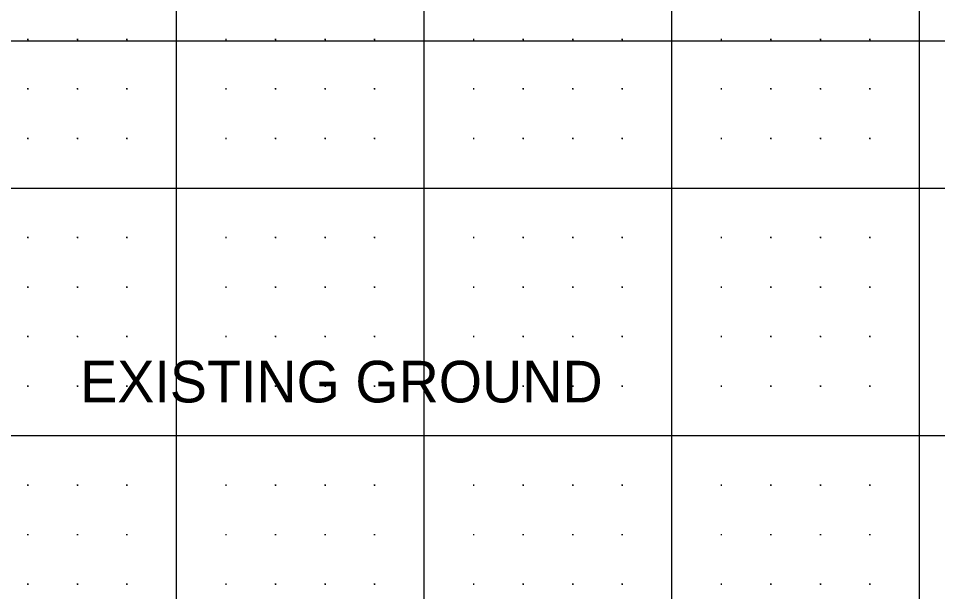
# Model space of a CAD drawing. Extents: x 471 to 2121, y 140 to 650.
# Drawn here: x 1754.2 to 1939.7, y 418.5 to 534.3 of the extents above; entities that cross this region are included whole.
import ezdxf

# ---------------------------------------------------------------- set-up
doc = ezdxf.new("R2010")
doc.units = 0
for name, color, linetype in [('Default', 7, 'Continuous'), ('DSN_DRFT_Border Grid', 7, 'Continuous'), ('Transition Dimensions', 7, 'Continuous')]:
    doc.layers.add(name, color=color, linetype=linetype)

msp = doc.modelspace()

# ---------------------------------------------------------------- linework, layer by layer
at = {"layer": 'DSN_DRFT_Border Grid'}
for p, q in [((1786.06, 150), (1786.06, 650)), ((1786.06, 150), (1786.06, 650)), ((1836.06, 150), (1836.06, 650)), ((1836.06, 150), (1836.06, 650)), ((1886.06, 150), (1886.06, 650)), ((1886.06, 150), (1886.06, 650)), ((1936.06, 150), (1936.06, 650)), ((1936.06, 150), (1936.06, 650)), ((1756.18, 530), (1755.94, 530)), ((1756.18, 530), (1755.94, 530)), ((1756.06, 530.12), (1756.06, 529.88)), ((1756.06, 530.12), (1756.06, 529.88)), ((1766.18, 530), (1765.94, 530)), ((1766.18, 530), (1765.94, 530)), ((1766.06, 530.12), (1766.06, 529.88)), ((1766.06, 530.12), (1766.06, 529.88)), ((1776.18, 530), (1775.94, 530)), ((1776.18, 530), (1775.94, 530)), ((1776.06, 530.12), (1776.06, 529.88)), ((1776.06, 530.12), (1776.06, 529.88)), ((1796.18, 530), (1795.94, 530)), ((1796.18, 530), (1795.94, 530)), ((1796.06, 530.12), (1796.06, 529.88)), ((1796.06, 530.12), (1796.06, 529.88)), ((1806.18, 530), (1805.94, 530)), ((1806.18, 530), (1805.94, 530)), ((1806.06, 530.12), (1806.06, 529.88)), ((1806.06, 530.12), (1806.06, 529.88)), ((1816.18, 530), (1815.94, 530)), ((1816.18, 530), (1815.94, 530)), ((1816.06, 530.12), (1816.06, 529.88)), ((1816.06, 530.12), (1816.06, 529.88)), ((1826.18, 530), (1825.94, 530)), ((1826.18, 530), (1825.94, 530)), ((1826.06, 530.12), (1826.06, 529.88)), ((1826.06, 530.12), (1826.06, 529.88)), ((1846.18, 530), (1845.94, 530)), ((1846.18, 530), (1845.94, 530)), ((1846.06, 530.12), (1846.06, 529.88)), ((1846.06, 530.12), (1846.06, 529.88)), ((1856.18, 530), (1855.94, 530)), ((1856.18, 530), (1855.94, 530)), ((1856.06, 530.12), (1856.06, 529.88)), ((1856.06, 530.12), (1856.06, 529.88)), ((1866.18, 530), (1865.94, 530)), ((1866.18, 530), (1865.94, 530)), ((1866.06, 530.12), (1866.06, 529.88)), ((1866.06, 530.12), (1866.06, 529.88)), ((1876.18, 530), (1875.94, 530)), ((1876.18, 530), (1875.94, 530)), ((1876.06, 530.12), (1876.06, 529.88)), ((1876.06, 530.12), (1876.06, 529.88)), ((1896.18, 530), (1895.94, 530)), ((1896.18, 530), (1895.94, 530)), ((1896.06, 530.12), (1896.06, 529.88)), ((1896.06, 530.12), (1896.06, 529.88)), ((1906.18, 530), (1905.94, 530)), ((1906.18, 530), (1905.94, 530)), ((1906.06, 530.12), (1906.06, 529.88)), ((1906.06, 530.12), (1906.06, 529.88)), ((1916.18, 530), (1915.94, 530)), ((1916.18, 530), (1915.94, 530)), ((1916.06, 530.12), (1916.06, 529.88)), ((1916.06, 530.12), (1916.06, 529.88)), ((1926.18, 530), (1925.94, 530)), ((1926.18, 530), (1925.94, 530)), ((1926.06, 530.12), (1926.06, 529.88)), ((1926.06, 530.12), (1926.06, 529.88)), ((1756.18, 520), (1755.94, 520)), ((1756.18, 520), (1755.94, 520)), ((1756.06, 520.12), (1756.06, 519.88)), ((1756.06, 520.12), (1756.06, 519.88)), ((1766.18, 520), (1765.94, 520)), ((1766.18, 520), (1765.94, 520)), ((1766.06, 520.12), (1766.06, 519.88)), ((1766.06, 520.12), (1766.06, 519.88)), ((1776.18, 520), (1775.94, 520)), ((1776.18, 520), (1775.94, 520)), ((1776.06, 520.12), (1776.06, 519.88)), ((1776.06, 520.12), (1776.06, 519.88)), ((1796.18, 520), (1795.94, 520)), ((1796.18, 520), (1795.94, 520)), ((1796.06, 520.12), (1796.06, 519.88)), ((1796.06, 520.12), (1796.06, 519.88)), ((1806.18, 520), (1805.94, 520)), ((1806.18, 520), (1805.94, 520)), ((1806.06, 520.12), (1806.06, 519.88)), ((1806.06, 520.12), (1806.06, 519.88)), ((1816.18, 520), (1815.94, 520)), ((1816.18, 520), (1815.94, 520)), ((1816.06, 520.12), (1816.06, 519.88)), ((1816.06, 520.12), (1816.06, 519.88)), ((1826.18, 520), (1825.94, 520)), ((1826.18, 520), (1825.94, 520)), ((1826.06, 520.12), (1826.06, 519.88)), ((1826.06, 520.12), (1826.06, 519.88)), ((1846.18, 520), (1845.94, 520)), ((1846.18, 520), (1845.94, 520)), ((1846.06, 520.12), (1846.06, 519.88)), ((1846.06, 520.12), (1846.06, 519.88)), ((1856.18, 520), (1855.94, 520)), ((1856.18, 520), (1855.94, 520)), ((1856.06, 520.12), (1856.06, 519.88)), ((1856.06, 520.12), (1856.06, 519.88)), ((1866.18, 520), (1865.94, 520)), ((1866.18, 520), (1865.94, 520)), ((1866.06, 520.12), (1866.06, 519.88)), ((1866.06, 520.12), (1866.06, 519.88)), ((1876.18, 520), (1875.94, 520)), ((1876.18, 520), (1875.94, 520)), ((1876.06, 520.12), (1876.06, 519.88)), ((1876.06, 520.12), (1876.06, 519.88)), ((1896.18, 520), (1895.94, 520)), ((1896.18, 520), (1895.94, 520)), ((1896.06, 520.12), (1896.06, 519.88)), ((1896.06, 520.12), (1896.06, 519.88)), ((1906.18, 520), (1905.94, 520)), ((1906.18, 520), (1905.94, 520)), ((1906.06, 520.12), (1906.06, 519.88)), ((1906.06, 520.12), (1906.06, 519.88)), ((1916.18, 520), (1915.94, 520)), ((1916.18, 520), (1915.94, 520)), ((1916.06, 520.12), (1916.06, 519.88)), ((1916.06, 520.12), (1916.06, 519.88)), ((1926.18, 520), (1925.94, 520)), ((1926.18, 520), (1925.94, 520)), ((1926.06, 520.12), (1926.06, 519.88)), ((1926.06, 520.12), (1926.06, 519.88)), ((1756.18, 510), (1755.94, 510)), ((1756.18, 510), (1755.94, 510)), ((1756.06, 510.12), (1756.06, 509.88)), ((1756.06, 510.12), (1756.06, 509.88)), ((1766.18, 510), (1765.94, 510)), ((1766.18, 510), (1765.94, 510)), ((1766.06, 510.12), (1766.06, 509.88)), ((1766.06, 510.12), (1766.06, 509.88)), ((1776.18, 510), (1775.94, 510)), ((1776.18, 510), (1775.94, 510)), ((1776.06, 510.12), (1776.06, 509.88)), ((1776.06, 510.12), (1776.06, 509.88)), ((1796.18, 510), (1795.94, 510)), ((1796.18, 510), (1795.94, 510)), ((1796.06, 510.12), (1796.06, 509.88)), ((1796.06, 510.12), (1796.06, 509.88)), ((1806.18, 510), (1805.94, 510)), ((1806.18, 510), (1805.94, 510)), ((1806.06, 510.12), (1806.06, 509.88)), ((1806.06, 510.12), (1806.06, 509.88)), ((1816.18, 510), (1815.94, 510)), ((1816.18, 510), (1815.94, 510)), ((1816.06, 510.12), (1816.06, 509.88)), ((1816.06, 510.12), (1816.06, 509.88)), ((1826.18, 510), (1825.94, 510)), ((1826.18, 510), (1825.94, 510)), ((1826.06, 510.12), (1826.06, 509.88)), ((1826.06, 510.12), (1826.06, 509.88)), ((1846.18, 510), (1845.94, 510)), ((1846.18, 510), (1845.94, 510)), ((1846.06, 510.12), (1846.06, 509.88)), ((1846.06, 510.12), (1846.06, 509.88)), ((1856.18, 510), (1855.94, 510)), ((1856.18, 510), (1855.94, 510)), ((1856.06, 510.12), (1856.06, 509.88)), ((1856.06, 510.12), (1856.06, 509.88)), ((1866.18, 510), (1865.94, 510)), ((1866.18, 510), (1865.94, 510)), ((1866.06, 510.12), (1866.06, 509.88)), ((1866.06, 510.12), (1866.06, 509.88)), ((1876.18, 510), (1875.94, 510)), ((1876.18, 510), (1875.94, 510)), ((1876.06, 510.12), (1876.06, 509.88)), ((1876.06, 510.12), (1876.06, 509.88)), ((1896.18, 510), (1895.94, 510)), ((1896.18, 510), (1895.94, 510)), ((1896.06, 510.12), (1896.06, 509.88)), ((1896.06, 510.12), (1896.06, 509.88)), ((1906.18, 510), (1905.94, 510)), ((1906.18, 510), (1905.94, 510)), ((1906.06, 510.12), (1906.06, 509.88)), ((1906.06, 510.12), (1906.06, 509.88)), ((1916.18, 510), (1915.94, 510)), ((1916.18, 510), (1915.94, 510)), ((1916.06, 510.12), (1916.06, 509.88)), ((1916.06, 510.12), (1916.06, 509.88)), ((1926.18, 510), (1925.94, 510)), ((1926.18, 510), (1925.94, 510)), ((1926.06, 510.12), (1926.06, 509.88)), ((1926.06, 510.12), (1926.06, 509.88)), ((521.06, 500), (2071.06, 500)), ((521.06, 500), (2071.06, 500)), ((1756.18, 490), (1755.94, 490)), ((1756.18, 490), (1755.94, 490)), ((1756.06, 490.12), (1756.06, 489.88)), ((1756.06, 490.12), (1756.06, 489.88)), ((1766.18, 490), (1765.94, 490)), ((1766.18, 490), (1765.94, 490)), ((1766.06, 490.12), (1766.06, 489.88)), ((1766.06, 490.12), (1766.06, 489.88)), ((1776.18, 490), (1775.94, 490)), ((1776.18, 490), (1775.94, 490)), ((1776.06, 490.12), (1776.06, 489.88)), ((1776.06, 490.12), (1776.06, 489.88)), ((1796.18, 490), (1795.94, 490)), ((1796.18, 490), (1795.94, 490)), ((1796.06, 490.12), (1796.06, 489.88)), ((1796.06, 490.12), (1796.06, 489.88)), ((1806.18, 490), (1805.94, 490)), ((1806.18, 490), (1805.94, 490)), ((1806.06, 490.12), (1806.06, 489.88)), ((1806.06, 490.12), (1806.06, 489.88)), ((1816.18, 490), (1815.94, 490)), ((1816.18, 490), (1815.94, 490)), ((1816.06, 490.12), (1816.06, 489.88)), ((1816.06, 490.12), (1816.06, 489.88)), ((1826.18, 490), (1825.94, 490)), ((1826.18, 490), (1825.94, 490)), ((1826.06, 490.12), (1826.06, 489.88)), ((1826.06, 490.12), (1826.06, 489.88)), ((1846.18, 490), (1845.94, 490)), ((1846.18, 490), (1845.94, 490)), ((1846.06, 490.12), (1846.06, 489.88)), ((1846.06, 490.12), (1846.06, 489.88)), ((1856.18, 490), (1855.94, 490)), ((1856.18, 490), (1855.94, 490)), ((1856.06, 490.12), (1856.06, 489.88)), ((1856.06, 490.12), (1856.06, 489.88)), ((1866.18, 490), (1865.94, 490)), ((1866.18, 490), (1865.94, 490)), ((1866.06, 490.12), (1866.06, 489.88)), ((1866.06, 490.12), (1866.06, 489.88)), ((1876.18, 490), (1875.94, 490)), ((1876.18, 490), (1875.94, 490)), ((1876.06, 490.12), (1876.06, 489.88)), ((1876.06, 490.12), (1876.06, 489.88)), ((1896.18, 490), (1895.94, 490)), ((1896.18, 490), (1895.94, 490)), ((1896.06, 490.12), (1896.06, 489.88)), ((1896.06, 490.12), (1896.06, 489.88)), ((1906.18, 490), (1905.94, 490)), ((1906.18, 490), (1905.94, 490)), ((1906.06, 490.12), (1906.06, 489.88)), ((1906.06, 490.12), (1906.06, 489.88)), ((1916.18, 490), (1915.94, 490)), ((1916.18, 490), (1915.94, 490)), ((1916.06, 490.12), (1916.06, 489.88)), ((1916.06, 490.12), (1916.06, 489.88)), ((1926.18, 490), (1925.94, 490)), ((1926.18, 490), (1925.94, 490)), ((1926.06, 490.12), (1926.06, 489.88)), ((1926.06, 490.12), (1926.06, 489.88)), ((1756.18, 480), (1755.94, 480)), ((1756.18, 480), (1755.94, 480)), ((1756.06, 480.12), (1756.06, 479.88)), ((1756.06, 480.12), (1756.06, 479.88)), ((1766.18, 480), (1765.94, 480)), ((1766.18, 480), (1765.94, 480)), ((1766.06, 480.12), (1766.06, 479.88)), ((1766.06, 480.12), (1766.06, 479.88)), ((1776.18, 480), (1775.94, 480)), ((1776.18, 480), (1775.94, 480)), ((1776.06, 480.12), (1776.06, 479.88)), ((1776.06, 480.12), (1776.06, 479.88)), ((1796.18, 480), (1795.94, 480)), ((1796.18, 480), (1795.94, 480)), ((1796.06, 480.12), (1796.06, 479.88)), ((1796.06, 480.12), (1796.06, 479.88)), ((1806.18, 480), (1805.94, 480)), ((1806.18, 480), (1805.94, 480)), ((1806.06, 480.12), (1806.06, 479.88)), ((1806.06, 480.12), (1806.06, 479.88)), ((1816.18, 480), (1815.94, 480)), ((1816.18, 480), (1815.94, 480)), ((1816.06, 480.12), (1816.06, 479.88)), ((1816.06, 480.12), (1816.06, 479.88)), ((1826.18, 480), (1825.94, 480)), ((1826.18, 480), (1825.94, 480)), ((1826.06, 480.12), (1826.06, 479.88)), ((1826.06, 480.12), (1826.06, 479.88)), ((1846.18, 480), (1845.94, 480)), ((1846.18, 480), (1845.94, 480)), ((1846.06, 480.12), (1846.06, 479.88)), ((1846.06, 480.12), (1846.06, 479.88)), ((1856.18, 480), (1855.94, 480)), ((1856.18, 480), (1855.94, 480)), ((1856.06, 480.12), (1856.06, 479.88)), ((1856.06, 480.12), (1856.06, 479.88)), ((1866.18, 480), (1865.94, 480)), ((1866.18, 480), (1865.94, 480)), ((1866.06, 480.12), (1866.06, 479.88)), ((1866.06, 480.12), (1866.06, 479.88)), ((1876.18, 480), (1875.94, 480)), ((1876.18, 480), (1875.94, 480)), ((1876.06, 480.12), (1876.06, 479.88)), ((1876.06, 480.12), (1876.06, 479.88)), ((1896.18, 480), (1895.94, 480)), ((1896.18, 480), (1895.94, 480)), ((1896.06, 480.12), (1896.06, 479.88)), ((1896.06, 480.12), (1896.06, 479.88)), ((1906.18, 480), (1905.94, 480)), ((1906.18, 480), (1905.94, 480)), ((1906.06, 480.12), (1906.06, 479.88)), ((1906.06, 480.12), (1906.06, 479.88)), ((1916.18, 480), (1915.94, 480)), ((1916.18, 480), (1915.94, 480)), ((1916.06, 480.12), (1916.06, 479.88)), ((1916.06, 480.12), (1916.06, 479.88)), ((1926.18, 480), (1925.94, 480)), ((1926.18, 480), (1925.94, 480)), ((1926.06, 480.12), (1926.06, 479.88)), ((1926.06, 480.12), (1926.06, 479.88)), ((1756.18, 470), (1755.94, 470)), ((1756.18, 470), (1755.94, 470)), ((1756.06, 470.12), (1756.06, 469.88)), ((1756.06, 470.12), (1756.06, 469.88)), ((1766.18, 470), (1765.94, 470)), ((1766.18, 470), (1765.94, 470)), ((1766.06, 470.12), (1766.06, 469.88)), ((1766.06, 470.12), (1766.06, 469.88)), ((1776.18, 470), (1775.94, 470)), ((1776.18, 470), (1775.94, 470)), ((1776.06, 470.12), (1776.06, 469.88)), ((1776.06, 470.12), (1776.06, 469.88)), ((1796.18, 470), (1795.94, 470)), ((1796.18, 470), (1795.94, 470)), ((1796.06, 470.12), (1796.06, 469.88)), ((1796.06, 470.12), (1796.06, 469.88)), ((1806.18, 470), (1805.94, 470)), ((1806.18, 470), (1805.94, 470)), ((1806.06, 470.12), (1806.06, 469.88)), ((1806.06, 470.12), (1806.06, 469.88)), ((1816.18, 470), (1815.94, 470)), ((1816.18, 470), (1815.94, 470)), ((1816.06, 470.12), (1816.06, 469.88)), ((1816.06, 470.12), (1816.06, 469.88)), ((1826.18, 470), (1825.94, 470)), ((1826.18, 470), (1825.94, 470)), ((1826.06, 470.12), (1826.06, 469.88)), ((1826.06, 470.12), (1826.06, 469.88)), ((1846.18, 470), (1845.94, 470)), ((1846.18, 470), (1845.94, 470)), ((1846.06, 470.12), (1846.06, 469.88)), ((1846.06, 470.12), (1846.06, 469.88)), ((1856.18, 470), (1855.94, 470)), ((1856.18, 470), (1855.94, 470)), ((1856.06, 470.12), (1856.06, 469.88)), ((1856.06, 470.12), (1856.06, 469.88)), ((1866.18, 470), (1865.94, 470)), ((1866.18, 470), (1865.94, 470)), ((1866.06, 470.12), (1866.06, 469.88)), ((1866.06, 470.12), (1866.06, 469.88)), ((1876.18, 470), (1875.94, 470)), ((1876.18, 470), (1875.94, 470)), ((1876.06, 470.12), (1876.06, 469.88)), ((1876.06, 470.12), (1876.06, 469.88)), ((1896.18, 470), (1895.94, 470)), ((1896.18, 470), (1895.94, 470)), ((1896.06, 470.12), (1896.06, 469.88)), ((1896.06, 470.12), (1896.06, 469.88)), ((1906.18, 470), (1905.94, 470)), ((1906.18, 470), (1905.94, 470)), ((1906.06, 470.12), (1906.06, 469.88)), ((1906.06, 470.12), (1906.06, 469.88)), ((1916.18, 470), (1915.94, 470)), ((1916.18, 470), (1915.94, 470)), ((1916.06, 470.12), (1916.06, 469.88)), ((1916.06, 470.12), (1916.06, 469.88)), ((1926.18, 470), (1925.94, 470)), ((1926.18, 470), (1925.94, 470)), ((1926.06, 470.12), (1926.06, 469.88)), ((1926.06, 470.12), (1926.06, 469.88)), ((1756.18, 460), (1755.94, 460)), ((1756.18, 460), (1755.94, 460)), ((1756.06, 460.12), (1756.06, 459.88)), ((1756.06, 460.12), (1756.06, 459.88)), ((1766.18, 460), (1765.94, 460)), ((1766.18, 460), (1765.94, 460)), ((1766.06, 460.12), (1766.06, 459.88)), ((1766.06, 460.12), (1766.06, 459.88)), ((1776.18, 460), (1775.94, 460)), ((1776.18, 460), (1775.94, 460)), ((1776.06, 460.12), (1776.06, 459.88)), ((1776.06, 460.12), (1776.06, 459.88)), ((1796.18, 460), (1795.94, 460)), ((1796.18, 460), (1795.94, 460)), ((1796.06, 460.12), (1796.06, 459.88)), ((1796.06, 460.12), (1796.06, 459.88)), ((1806.18, 460), (1805.94, 460)), ((1806.18, 460), (1805.94, 460)), ((1806.06, 460.12), (1806.06, 459.88)), ((1806.06, 460.12), (1806.06, 459.88)), ((1816.18, 460), (1815.94, 460)), ((1816.18, 460), (1815.94, 460)), ((1816.06, 460.12), (1816.06, 459.88)), ((1816.06, 460.12), (1816.06, 459.88)), ((1826.18, 460), (1825.94, 460)), ((1826.18, 460), (1825.94, 460)), ((1826.06, 460.12), (1826.06, 459.88)), ((1826.06, 460.12), (1826.06, 459.88)), ((1846.18, 460), (1845.94, 460)), ((1846.18, 460), (1845.94, 460)), ((1846.06, 460.12), (1846.06, 459.88)), ((1846.06, 460.12), (1846.06, 459.88)), ((1856.18, 460), (1855.94, 460)), ((1856.18, 460), (1855.94, 460)), ((1856.06, 460.12), (1856.06, 459.88)), ((1856.06, 460.12), (1856.06, 459.88)), ((1866.18, 460), (1865.94, 460)), ((1866.18, 460), (1865.94, 460)), ((1866.06, 460.12), (1866.06, 459.88)), ((1866.06, 460.12), (1866.06, 459.88)), ((1876.18, 460), (1875.94, 460)), ((1876.18, 460), (1875.94, 460)), ((1876.06, 460.12), (1876.06, 459.88)), ((1876.06, 460.12), (1876.06, 459.88)), ((1896.18, 460), (1895.94, 460)), ((1896.18, 460), (1895.94, 460)), ((1896.06, 460.12), (1896.06, 459.88)), ((1896.06, 460.12), (1896.06, 459.88)), ((1906.18, 460), (1905.94, 460)), ((1906.18, 460), (1905.94, 460)), ((1906.06, 460.12), (1906.06, 459.88)), ((1906.06, 460.12), (1906.06, 459.88)), ((1916.18, 460), (1915.94, 460)), ((1916.18, 460), (1915.94, 460)), ((1916.06, 460.12), (1916.06, 459.88)), ((1916.06, 460.12), (1916.06, 459.88)), ((1926.18, 460), (1925.94, 460)), ((1926.18, 460), (1925.94, 460)), ((1926.06, 460.12), (1926.06, 459.88)), ((1926.06, 460.12), (1926.06, 459.88)), ((521.06, 450), (2071.06, 450)), ((521.06, 450), (2071.06, 450)), ((1756.18, 440), (1755.94, 440)), ((1756.18, 440), (1755.94, 440)), ((1756.06, 440.12), (1756.06, 439.88)), ((1756.06, 440.12), (1756.06, 439.88)), ((1766.18, 440), (1765.94, 440)), ((1766.18, 440), (1765.94, 440)), ((1766.06, 440.12), (1766.06, 439.88)), ((1766.06, 440.12), (1766.06, 439.88)), ((1776.18, 440), (1775.94, 440)), ((1776.18, 440), (1775.94, 440)), ((1776.06, 440.12), (1776.06, 439.88)), ((1776.06, 440.12), (1776.06, 439.88)), ((1796.18, 440), (1795.94, 440)), ((1796.18, 440), (1795.94, 440)), ((1796.06, 440.12), (1796.06, 439.88)), ((1796.06, 440.12), (1796.06, 439.88)), ((1806.18, 440), (1805.94, 440)), ((1806.18, 440), (1805.94, 440)), ((1806.06, 440.12), (1806.06, 439.88)), ((1806.06, 440.12), (1806.06, 439.88)), ((1816.18, 440), (1815.94, 440)), ((1816.18, 440), (1815.94, 440)), ((1816.06, 440.12), (1816.06, 439.88)), ((1816.06, 440.12), (1816.06, 439.88)), ((1826.18, 440), (1825.94, 440)), ((1826.18, 440), (1825.94, 440)), ((1826.06, 440.12), (1826.06, 439.88)), ((1826.06, 440.12), (1826.06, 439.88)), ((1846.18, 440), (1845.94, 440)), ((1846.18, 440), (1845.94, 440)), ((1846.06, 440.12), (1846.06, 439.88)), ((1846.06, 440.12), (1846.06, 439.88)), ((1856.18, 440), (1855.94, 440)), ((1856.18, 440), (1855.94, 440)), ((1856.06, 440.12), (1856.06, 439.88)), ((1856.06, 440.12), (1856.06, 439.88)), ((1866.18, 440), (1865.94, 440)), ((1866.18, 440), (1865.94, 440)), ((1866.06, 440.12), (1866.06, 439.88)), ((1866.06, 440.12), (1866.06, 439.88)), ((1876.18, 440), (1875.94, 440)), ((1876.18, 440), (1875.94, 440)), ((1876.06, 440.12), (1876.06, 439.88)), ((1876.06, 440.12), (1876.06, 439.88)), ((1896.18, 440), (1895.94, 440)), ((1896.18, 440), (1895.94, 440)), ((1896.06, 440.12), (1896.06, 439.88)), ((1896.06, 440.12), (1896.06, 439.88)), ((1906.18, 440), (1905.94, 440)), ((1906.18, 440), (1905.94, 440)), ((1906.06, 440.12), (1906.06, 439.88)), ((1906.06, 440.12), (1906.06, 439.88)), ((1916.18, 440), (1915.94, 440)), ((1916.18, 440), (1915.94, 440)), ((1916.06, 440.12), (1916.06, 439.88)), ((1916.06, 440.12), (1916.06, 439.88)), ((1926.18, 440), (1925.94, 440)), ((1926.18, 440), (1925.94, 440)), ((1926.06, 440.12), (1926.06, 439.88)), ((1926.06, 440.12), (1926.06, 439.88)), ((1756.18, 430), (1755.94, 430)), ((1756.18, 430), (1755.94, 430)), ((1756.06, 430.12), (1756.06, 429.88)), ((1756.06, 430.12), (1756.06, 429.88)), ((1766.18, 430), (1765.94, 430)), ((1766.18, 430), (1765.94, 430)), ((1766.06, 430.12), (1766.06, 429.88)), ((1766.06, 430.12), (1766.06, 429.88)), ((1776.18, 430), (1775.94, 430)), ((1776.18, 430), (1775.94, 430)), ((1776.06, 430.12), (1776.06, 429.88)), ((1776.06, 430.12), (1776.06, 429.88)), ((1796.18, 430), (1795.94, 430)), ((1796.18, 430), (1795.94, 430)), ((1796.06, 430.12), (1796.06, 429.88)), ((1796.06, 430.12), (1796.06, 429.88)), ((1806.18, 430), (1805.94, 430)), ((1806.18, 430), (1805.94, 430)), ((1806.06, 430.12), (1806.06, 429.88)), ((1806.06, 430.12), (1806.06, 429.88)), ((1816.18, 430), (1815.94, 430)), ((1816.18, 430), (1815.94, 430)), ((1816.06, 430.12), (1816.06, 429.88)), ((1816.06, 430.12), (1816.06, 429.88)), ((1826.18, 430), (1825.94, 430)), ((1826.18, 430), (1825.94, 430)), ((1826.06, 430.12), (1826.06, 429.88)), ((1826.06, 430.12), (1826.06, 429.88)), ((1846.18, 430), (1845.94, 430)), ((1846.18, 430), (1845.94, 430)), ((1846.06, 430.12), (1846.06, 429.88)), ((1846.06, 430.12), (1846.06, 429.88)), ((1856.18, 430), (1855.94, 430)), ((1856.18, 430), (1855.94, 430)), ((1856.06, 430.12), (1856.06, 429.88)), ((1856.06, 430.12), (1856.06, 429.88)), ((1866.18, 430), (1865.94, 430)), ((1866.18, 430), (1865.94, 430)), ((1866.06, 430.12), (1866.06, 429.88)), ((1866.06, 430.12), (1866.06, 429.88)), ((1876.18, 430), (1875.94, 430)), ((1876.18, 430), (1875.94, 430)), ((1876.06, 430.12), (1876.06, 429.88)), ((1876.06, 430.12), (1876.06, 429.88)), ((1896.18, 430), (1895.94, 430)), ((1896.18, 430), (1895.94, 430)), ((1896.06, 430.12), (1896.06, 429.88)), ((1896.06, 430.12), (1896.06, 429.88)), ((1906.18, 430), (1905.94, 430)), ((1906.18, 430), (1905.94, 430)), ((1906.06, 430.12), (1906.06, 429.88)), ((1906.06, 430.12), (1906.06, 429.88)), ((1916.18, 430), (1915.94, 430)), ((1916.18, 430), (1915.94, 430)), ((1916.06, 430.12), (1916.06, 429.88)), ((1916.06, 430.12), (1916.06, 429.88)), ((1926.18, 430), (1925.94, 430)), ((1926.18, 430), (1925.94, 430)), ((1926.06, 430.12), (1926.06, 429.88)), ((1926.06, 430.12), (1926.06, 429.88)), ((1756.18, 420), (1755.94, 420)), ((1756.18, 420), (1755.94, 420)), ((1756.06, 420.12), (1756.06, 419.88)), ((1756.06, 420.12), (1756.06, 419.88)), ((1766.18, 420), (1765.94, 420)), ((1766.18, 420), (1765.94, 420)), ((1766.06, 420.12), (1766.06, 419.88)), ((1766.06, 420.12), (1766.06, 419.88)), ((1776.18, 420), (1775.94, 420)), ((1776.18, 420), (1775.94, 420)), ((1776.06, 420.12), (1776.06, 419.88)), ((1776.06, 420.12), (1776.06, 419.88)), ((1796.18, 420), (1795.94, 420)), ((1796.18, 420), (1795.94, 420)), ((1796.06, 420.12), (1796.06, 419.88)), ((1796.06, 420.12), (1796.06, 419.88)), ((1806.18, 420), (1805.94, 420)), ((1806.18, 420), (1805.94, 420)), ((1806.06, 420.12), (1806.06, 419.88)), ((1806.06, 420.12), (1806.06, 419.88)), ((1816.18, 420), (1815.94, 420)), ((1816.18, 420), (1815.94, 420)), ((1816.06, 420.12), (1816.06, 419.88)), ((1816.06, 420.12), (1816.06, 419.88)), ((1826.18, 420), (1825.94, 420)), ((1826.18, 420), (1825.94, 420)), ((1826.06, 420.12), (1826.06, 419.88)), ((1826.06, 420.12), (1826.06, 419.88)), ((1846.18, 420), (1845.94, 420)), ((1846.18, 420), (1845.94, 420)), ((1846.06, 420.12), (1846.06, 419.88)), ((1846.06, 420.12), (1846.06, 419.88)), ((1856.18, 420), (1855.94, 420)), ((1856.18, 420), (1855.94, 420)), ((1856.06, 420.12), (1856.06, 419.88)), ((1856.06, 420.12), (1856.06, 419.88)), ((1866.18, 420), (1865.94, 420)), ((1866.18, 420), (1865.94, 420)), ((1866.06, 420.12), (1866.06, 419.88)), ((1866.06, 420.12), (1866.06, 419.88)), ((1876.18, 420), (1875.94, 420)), ((1876.18, 420), (1875.94, 420)), ((1876.06, 420.12), (1876.06, 419.88)), ((1876.06, 420.12), (1876.06, 419.88)), ((1896.18, 420), (1895.94, 420)), ((1896.18, 420), (1895.94, 420)), ((1896.06, 420.12), (1896.06, 419.88)), ((1896.06, 420.12), (1896.06, 419.88)), ((1906.18, 420), (1905.94, 420)), ((1906.18, 420), (1905.94, 420)), ((1906.06, 420.12), (1906.06, 419.88)), ((1906.06, 420.12), (1906.06, 419.88)), ((1916.18, 420), (1915.94, 420)), ((1916.18, 420), (1915.94, 420)), ((1916.06, 420.12), (1916.06, 419.88)), ((1916.06, 420.12), (1916.06, 419.88)), ((1926.18, 420), (1925.94, 420)), ((1926.18, 420), (1925.94, 420)), ((1926.06, 420.12), (1926.06, 419.88)), ((1926.06, 420.12), (1926.06, 419.88))]:
    msp.add_line(p, q, dxfattribs=at)
at = {"layer": 'Transition Dimensions'}
msp.add_line((536.06, 529.75), (1956.06, 529.75), dxfattribs=at)

# ---------------------------------------------------------------- texts
at = {"layer": 'Default'}
msp.add_text('EXISTING GROUND', height=8.4, dxfattribs=at).set_placement((1766.63, 456.71))

doc.saveas('drawing.dxf')
